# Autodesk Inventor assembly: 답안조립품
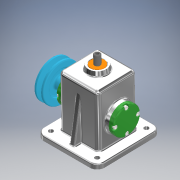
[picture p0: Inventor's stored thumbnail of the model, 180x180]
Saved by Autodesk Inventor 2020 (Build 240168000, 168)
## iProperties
Created: 2022-11
Part Number: 답안조립품
Document SubType Name: Assembly
Designer: com
Author: com
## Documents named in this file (16)
- C:\Users\com\Desktop\721106V1017\답안조립품.iam
- C:\Users\com\Desktop\721106V1017\본체.ipt
- C:\Users\com\Desktop\721106V1017\베어링 6201.ipt
- C:\Users\com\Desktop\721106V1017\편심축.ipt
- C:\Users\com\Desktop\721106V1017\뒤커버.ipt
- C:\Users\com\Desktop\721106V1017\앞커버.ipt
- C:\Users\com\Desktop\721106V1017\오일실 12 25 7.ipt
- C:\Users\com\Desktop\721106V1017\링크.ipt
- C:\Users\com\Desktop\721106V1017\부시.ipt
- C:\Users\com\Desktop\721106V1017\슬라이드.ipt
- C:\Users\com\Desktop\721106V1017\고정핀 1.2 x 10.ipt
- C:\Users\com\Desktop\721106V1017\핀 5 x 18.ipt
- C:\Users\com\Desktop\721106V1017\볼트 M4 x 12.ipt
- C:\Users\com\Desktop\721106V1017\키 4 x 4 x 15.ipt
- C:\Users\com\Desktop\721106V1017\V벨트풀리.ipt
- C:\Users\com\Desktop\721106V1017\멈춤나사 M3 x 8.ipt
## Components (11 placed, 4 different names)
1. 고정핀 1.2 x 10:1
2. 핀 5 x 18:1
3. V벨트풀리:1 — 각도:1
4. ISO 4762 M4 x 12:1
5. ISO 4762 M4 x 12:3
6. ISO 4762 M4 x 12:4
7. ISO 4762 M4 x 12:5
8. ISO 4762 M4 x 12:2
9. ISO 4762 M4 x 12:6
10. ISO 4762 M4 x 12:7
11. ISO 4762 M4 x 12:8
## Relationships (1: Angle 1)
- 각도:1 [Angle]: V벨트풀리:1
